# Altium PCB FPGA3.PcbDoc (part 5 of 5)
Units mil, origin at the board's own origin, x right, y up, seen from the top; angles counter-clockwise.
Board outline 4000 x 2750 mil, 12 copper layers (Top Layer, Plane1, MidLayer1, Plane2, MidLayer2, Plane3, Plane4, MidLayer 3, Plane5, MidLayer 4, Plane6, Bottom Layer), stack 57.29 mil thick; 420 components, 368 nets, 1889 pads, 1236 vias.
Unrouted connection lines stored in the file: 1.
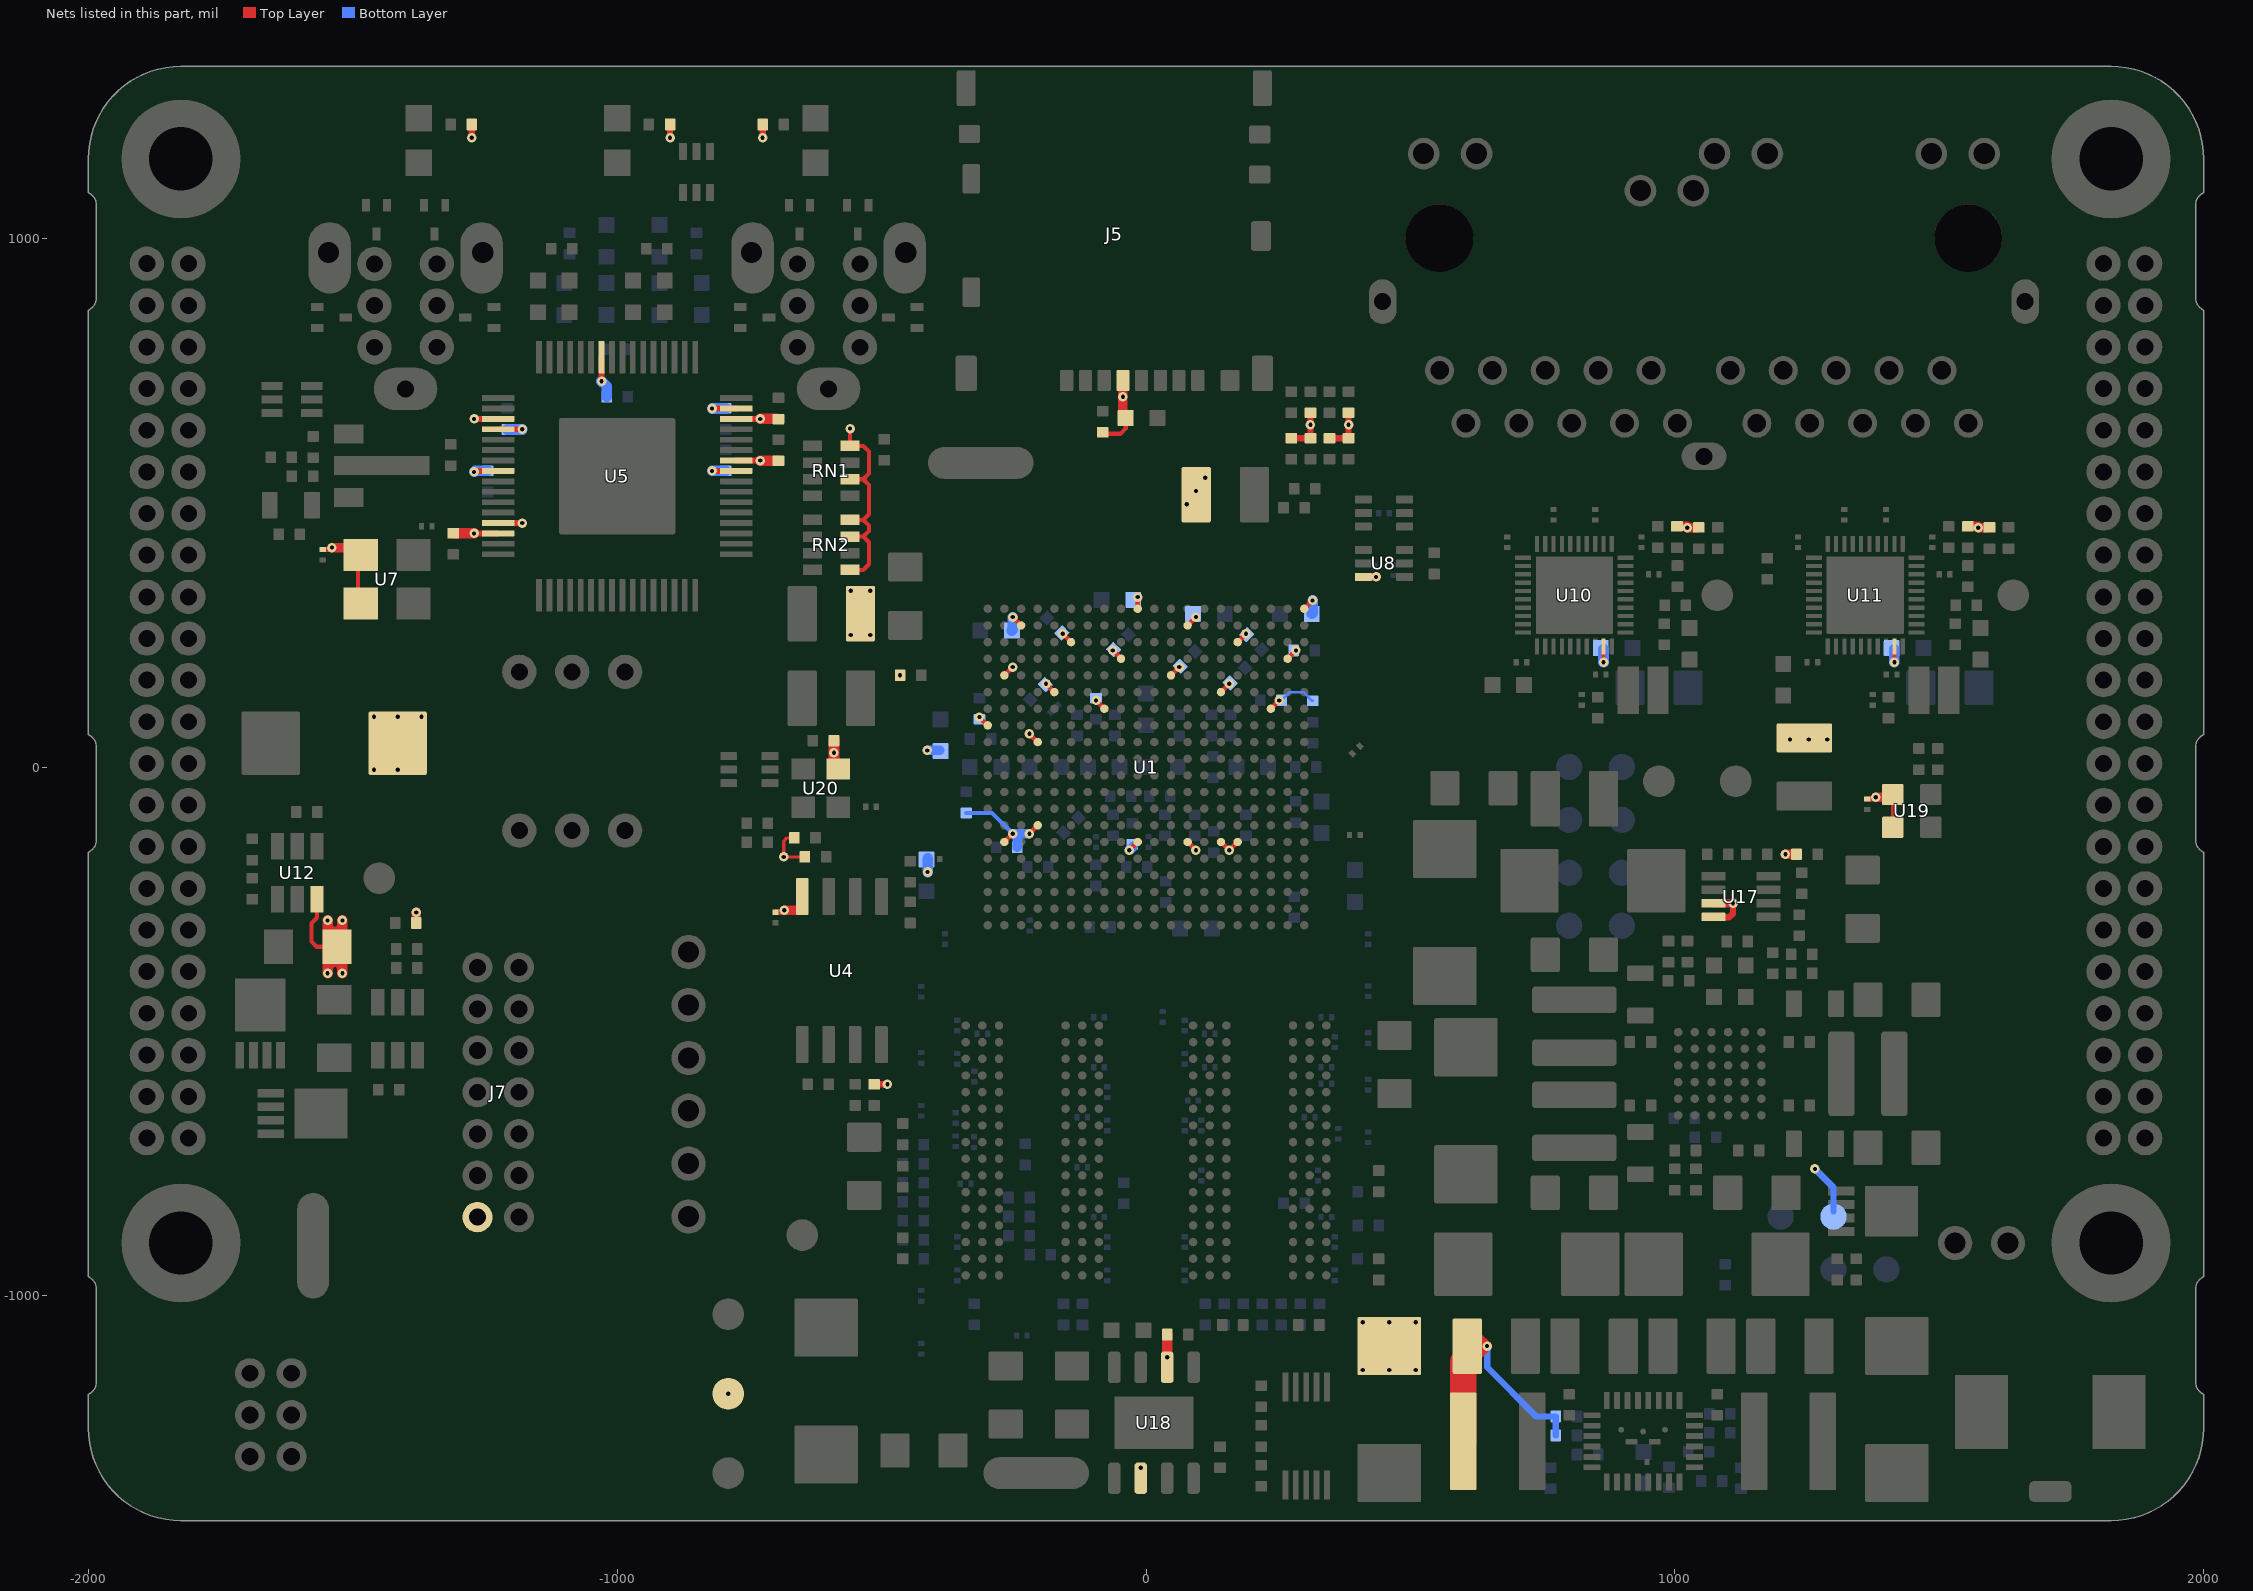
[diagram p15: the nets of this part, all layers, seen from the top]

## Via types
v1: diameter 18, hole 8, Top Layer to Bottom Layer, tented both sides, 1236 vias

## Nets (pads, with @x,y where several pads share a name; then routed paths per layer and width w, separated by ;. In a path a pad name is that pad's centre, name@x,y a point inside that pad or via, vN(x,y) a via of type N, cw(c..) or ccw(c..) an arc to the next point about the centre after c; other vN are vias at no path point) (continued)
VCC3: C5.1 C11.1 C12.1 C13.1 C14.1 C20.1 C26.1 C27.1 C28.1 C29.1 C30.1 C61.1 C62.1 C63.1 C64.1 C72.1 C73.1 CB72.1 CB73.1 CB74.1 CB75.1 CB88.1 CB89.1 CB90.1 CB91.1 CB92.1 CB94.1 CB96.1 CB97.1 CB100.1 CB101.1 CB104.1 CB105.1 CB116.1 CB123.1 CB124.1 CB125.1 CB126.1 CB129.1 CB130.1 CB131.1 CB132.1 J5.4 J7.2 L2.2 L13.2 L14.2 pad.0@-790,-1185 R41.1 R43.1 R46.2 R47.1 R48.2 R49.1 R50.1 R51.1 R52.1 R53.2 R54.2 R55.2 R60.2 R61.1 R64.1 R67.2 R68.1 R70.1 R86.1 R87.1 R104.1 R117.1 RN1.2 RN1.4 RN2.1 RN2.3 RN2.4 TP4.1 U1.A13 U1.B6 U1.B16 U1.C19 U1.D7 U1.D12 U1.E15 U1.F18 U1.H14 U1.J17 U1.K6 U1.K20 U1.M16 U1.N6 U1.N19 U1.R6 U1.R15 U1.T6 U1.T18 U1.V14 U1.W17 U1.Y20 U4.8 U5.25 U5.26 U5.30 U5.31 U5.42 U5.51 U5.52 U5.56 U5.61 U5.62 U7.1 U7.4 U8.6 U10.29 U11.29 U12.6 U17.7 U17.8 U18.2 U18.6 U19.1 U19.4 U20.4 | length 4275.1
  Top Layer w6: R86.1@-672,-141 R86.1@-665,-134 -679,-134 -685,-140 v1(-685,-170) R87.1@-645,-170 ; U20.4@-590,-4 U20.4@-584,-4 ; U19.1@1412,-114 U19.4@1412,-52
  Top Layer w7: U7.4@-1490.37,415 U7.4@-1490,414.63 ; U7.1@-1490,309 U7.4@-1490,399.63
  Top Layer w8: U12.6@-1567.5,-250 -1567.5,-285 -1578,-295.5 -1578,-330 -1568,-340 R117.1@-1533,-340 ; RN2.1@-559.5,372.76 -534.75,372.76 -524,383.5 -524,425 -534.75,435.75 ; RN2.3@-559.5,435.75 -534.75,435.75 ; RN2.4@-559.5,467.24 -534.75,467.24 ; RN1.2@-559.5,544.25 -534.75,544.25 ; v1(-559.5,640) RN1.4@-559.5,607.24 -534.75,607.24 -524,596.5 -524,555 -534.75,544.25 ; R67.2@-82,633 -79,630 -48.5,630 -38.5,640 CB132.1@-38.5,660 ; CB132.1@-43.7,670.7 CB132.1@-43,670 ; v1(865.12,198) U10.29@865.12,228 ; v1(1415.12,198) U11.29@1415.12,228 ; -534.75,435.75 -524,446.5 -524,456.5 -534.75,467.24 ; -534.75,467.24 -524,477.99 -524,533.5 -534.75,544.25
  Top Layer w9: v1(-314.96,94.49) U1.A13@-299.21,78.74 ; U1.B6@-267.72,-141.73 v1(-251.97,-125.98) ; U1.B16@-267.72,173.23 v1(-251.97,188.98) ; v1(-251.97,283.46) U1.C19@-236.22,267.72 ; v1(-220.47,-125.98) U1.D7@-204.72,-110.24 ; v1(-220.47,62.99) U1.D12@-204.72,47.24 ; v1(-188.98,157.48) U1.E15@-173.23,141.73 ; v1(-157.48,251.97) U1.F18@-141.73,236.22 ; v1(-94.49,125.98) U1.H14@-78.74,110.24 ; v1(-62.99,220.47) U1.J17@-47.24,204.72 ; v1(-31.5,-157.48) U1.K6@-15.75,-141.73 ; U1.K20@-15.75,299.21 v1(-15.75,321.48) ; U1.M16@47.24,173.23 v1(62.99,188.98) ; U1.N6@78.74,-141.73 v1(94.49,-157.48) ; U1.N19@78.74,267.72 v1(94.49,283.46) ; U1.R6@141.73,-141.73 v1(157.48,-157.48) U1.T6@173.23,-141.73 ; U1.R15@141.73,141.73 v1(157.48,157.48) ; U1.T18@173.23,236.22 v1(188.98,251.97) ; U1.V14@236.22,110.24 v1(251.97,125.98) ; U1.W17@267.72,204.72 v1(283.46,220.47) ; U1.Y20@299.21,299.21 v1(314.96,314.96)
  Top Layer w10: CB74.1@-1554.29,411.5 v1@-1539.29,411.5 ; v1@-1540.45,415 v1(-1539.37,415) v1@-1538.29,415 ; CB75.1@-698.92,-274.5 v1@-683.92,-274.5 ; v1@-685.08,-271 v1(-684,-271) v1@-682.92,-271 ; CB73.1@1364,-60.5 v1@1379,-60.5 ; v1@1377.84,-57 v1(1380,-57)
  Top Layer w11: v1(-1270.47,441.73) U5.62@-1225,441.73 ; v1@-1270.47,559.84 U5.56@-1225,559.84 ; v1(-1270.47,658.27) U5.51@-1225,658.27 ; U5.61@-1225,461.42 v1(-1179.53,461.42) ; U5.52@-1225,638.58 v1(-1179.53,638.58) ; v1(-1029.53,729.53) U5.42@-1029.53,775 ; v1(-820.47,559.84) U5.25@-775,559.84 ; v1(-820.47,677.95) U5.31@-775,677.95 ; U5.26@-775,579.53 v1(-729.53,579.53) ; U5.30@-775,658.27 v1(-729.53,658.27)
  Top Layer w12: v1(-1275,1190) R46.2@-1275,1215 ; v1(-900,1190) R47.1@-900,1215 ; v1(-725,1190) R48.2@-725,1215 ; R54.2@-514,-600 v1(-489,-600) ; R49.1@275,622 R50.1@311,622 v1(311,647) R41.1@311,670 ; R51.1@347,622 R52.1@383,622 v1(383,647) R43.1@383,670 ; U17.8@1073,-283.39 1073.57,-283.95 1102.97,-283.95 1110,-276.92 v1(1110,-257.8)
  Top Layer w15: U8.6@411,359.41 v1(435,359.41)
  Top Layer w16: U17.7@1073,-257.8 v1(1110,-257.8)
  Top Layer w18: v1@-1538.29,415 U7.4@-1490.37,415 ; R61.1@-1380,-295 v1(-1380,-275) ; v1(-684,-271) U4.8@-658,-271 ; CB132.1@-43.7,670.7 v1(-43.7,700) J5.4@-43.7,730.83 ; C64.1@627.32,-1112.68 v1(645,-1095) C64.1@627.32,-1077.32 ; L13.2@1004,455 v1@1023.5,455 ; v1(1023.5,452.5) R68.1@1043,452.5 ; v1(1209,-165) R64.1@1230,-165 ; v1(1380,-57) U19.4@1401,-57 ; L14.2@1554,455 v1@1573.5,455 ; v1(1573.5,452.5) R70.1@1593,452.5
  Top Layer w20: v1(-1547.5,-390) v1@-1547.5,-382 ; R117.1@-1547.5,-345 v1@-1547.5,-382 ; R117.1@-1547.5,-335 v1@-1547.5,-298.05 ; v1(-1547.5,-290) v1@-1547.5,-298 ; v1(-1519.5,-390) v1@-1519.5,-382 ; R117.1@-1519.5,-345 v1@-1519.5,-382 ; R117.1@-1519.5,-335 v1@-1519.5,-298.05 ; v1(-1519.5,-290) v1@-1519.5,-298 ; C11.1@-1310,442 -1309.73,441.73 v1(-1270.47,441.73) ; v1(-729.53,579.53) -695.31,579.53 C13.1@-695,579.21 ; v1(-729.53,658.27) C12.1@-698.06,658.27 ; U20.4@-590,-8 -590,-4 -590,2 v1(-590,27) C14.1@-590,50 ; U18.6@40,-1135 v1(40,-1116) 40,-1074 C20.1@40,-1073 ; v1@-1547.5,-382 cw(c-1533.5,-382) v1@-1519.5,-382 ; v1@-1547.5,-382 cw(c-1533.5,-382) v1@-1519.5,-382 ; v1@-1547.5,-298.05 ccw(c-1533.5,-298) v1@-1519.5,-298.05 ; v1@-1547.5,-298.05 ccw(c-1533.5,-298) v1@-1519.5,-298.05 ; v1@-1547.5,-298.05 cw(c-1533.5,-298) v1@-1547.5,-298 ; v1@-1547.5,-298.05 cw(c-1533.5,-298) v1@-1547.5,-298 ; v1@-1547.5,-298.05 v1@-1547.5,-298 ; v1@-1519.5,-298.05 ccw(c-1533.5,-298) v1@-1519.5,-298 ; v1@-1519.5,-298.05 ccw(c-1533.5,-298) v1@-1519.5,-298 ; v1@-1519.5,-298.05 v1@-1519.5,-298
  Top Layer w25: U20.4@-590,2 U20.4@-584,-4
  Top Layer w50: L2.2@600,-1275 C64.1@600,-1125
  Bottom Layer w5: CB97.1@256.22,125.98 271.97,141.73 298.27,141.73 306.5,133.5 306.5,132.5 314,125 R60.2@315,125
  Bottom Layer w8: R55.2@-340,-87 -290.95,-87 v1(-251.97,-125.98)
  Bottom Layer w12: v1(645,-1095) 645,-1135 738,-1228 C5.1@775,-1228 R104.1@775,-1264 ; v1(1265,-760) 1300,-795 TP4.1@1300,-840
  Bottom Layer w18: v1(-413.5,31.5) CB116.1@-390,31.5 ; v1(-251.97,-125.98) v1@-243.5,-125.98 ; CB90.1@-243.5,-152 v1@-243.5,-125.98 ; v1(-220.47,-125.98) v1@-243.5,-125.98 ; v1(-31.5,-157.48) CB94.1@-23.98,-149.97
  Bottom Layer w20: v1(-1270.47,558) -1268.47,560 C30.1@-1245,560 ; C29.1@-1208,638.27 -1179.84,638.27 v1(-1179.53,638.58) ; v1(-1029.53,729.53) -1020,720 C28.1@-1020,700 ; v1(-820.47,559.84) -820.31,560 C27.1@-795,560 ; v1(-820.47,677.95) -795.31,677.95 C26.1@-795,678.27 ; v1(-413,-198.5) CB129.1@-413,-173 ; CB125.1@-253.46,258 -251.97,259.5 v1(-251.97,283.46) ; CB123.1@313.46,289.5 314.96,291 v1(314.96,314.96) ; v1(865.12,198) CB130.1@865.12,223 ; v1(1415.12,198) CB131.1@1415.12,223
  other v1: -10,-1325 -790,-1185 410,-1140 460,-1140 510,-1140 410,-1050 460,-1050 510,-1050 -1460,-5 -1415,-5 1218,52 1253,52 1288,52 -1460,95 -1415,95 -1370,95 -465,173.5 -558.5,249.5 -521.5,249.5 -558.5,333.5 -521.5,333.5 77,497 94.5,522 112,547
pads on no net: J3.1 J4.1 J5.9 J5.10 J7.12 J7.14 J8.5 J8.6 J8.10A J8.10B J10.3 U1.A14 U1.A15 U1.A16 U1.A17 U1.A19 U1.B5 U1.B14 U1.B17 U1.B18 U1.C5 U1.C6 U1.C8 U1.C10 U1.C11 U1.C13 U1.C15 U1.C16 U1.C18 U1.D9 U1.D10 U1.D11 U1.D13 U1.D15 U1.E6 U1.E8 U1.E9 U1.E11 U1.E13 U1.E14 U1.E16 U1.F10 U1.F14 U1.F15 U1.N16 U2.J1 U2.J9 U2.L1 U2.L9 U2.M7 U3.J1 U3.J9 U3.L1 U3.L9 U3.M7 U5.3 U5.16 U5.60 U6.2 U6.4 U6.5 U10.32 U10.35 U11.32 U11.35 U14.6 U14.7 U15.E2 U15.E5 U16.6 U16.10 U16.27

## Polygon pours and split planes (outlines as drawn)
GND on MidLayer 4 "Mid4GND" (hatched 90Degree grid 8 track 8.1, remove dead copper, pour order 3): -2000,-1425 2000,-1425 2000,1325 -2000,1325
GND on MidLayer 3 "Mid3GND" (hatched 90Degree grid 8 track 8.1, remove dead copper, pour order 2): -2025,-1438 1975,-1438 1975,1312 -2025,1312
GND on MidLayer2 "Mid2GND" (hatched 90Degree grid 8 track 8.1, remove dead copper, pour order 1): -2000,-1425 2000,-1425 2000,1325 -2000,1325
GND on MidLayer1 "Mid1GND" (hatched 90Degree grid 8 track 8.1, remove dead copper, pour order 0): -2000,-1425 2000,-1425 2000,1325 -2000,1325
GND on Plane1 (split plane): 225 vertices, not listed, extent -1979.97,-1404.97 1979.97,1304.97
GND on Plane2 (split plane): 225 vertices, not listed, extent -1979.97,-1404.97 1979.97,1304.97
5V on Plane2 (split plane): -740.1,-5 -739.71,-6.95 -738.6,-8.6 -605.1,-142.11 -605.1,-890 -604.71,-891.95 -603.6,-893.6 -505.1,-992.11 -505.1,-1329.9 -1602.89,-1329.9 -1644.9,-1287.89 -1644.9,-282.11 -1581.4,-218.6 -1580.29,-216.95 -1579.9,-215 -1579.9,105 -1580.29,106.95 -1581.4,108.6 -1604.9,132.11 -1604.9,399.9 -740.1,399.9
V-FAULT_3 on Plane2 (split plane): -410.1,675 -409.71,673.05 -408.6,671.4 -358.6,621.4 -356.95,620.29 -355,619.9 829.9,619.9 829.9,570.1 -575,570.1 -576.95,569.71 -578.6,568.6 -737.11,410.1 -1604.9,410.1 -1604.9,1069.9 -410.1,1069.9
5V-DCDC_10 on Plane2 (split plane): 1519.9,-1287.89 1477.89,-1329.9 -494.9,-1329.9 -494.9,-1225.1 125,-1225.1 126.95,-1224.71 128.6,-1223.6 157.11,-1195.1 385,-1195.1 386.95,-1194.71 388.6,-1193.6 528.6,-1053.6 529.71,-1051.95 530.1,-1050 530.1,-430.1 935,-430.1 936.95,-429.71 938.6,-428.6 988.6,-378.6 1102.11,-265.1 1519.9,-265.1
0.75V on Plane2 (split plane): 261.4,-163.6 263.05,-164.71 265,-165.1 297.89,-165.1 506.4,-373.6 519.9,-387.11 519.9,-1047.89 382.89,-1184.9 155,-1184.9 153.05,-1185.29 151.4,-1186.4 122.89,-1214.9 -494.9,-1214.9 -494.9,-990 -495.29,-988.05 -496.4,-986.4 -594.9,-887.89 -594.9,-145.1 242.89,-145.1
1.8V on Plane2 (split plane): 1519.9,317.89 1519.9,-254.9 1100,-254.9 1098.05,-255.29 1096.4,-256.4 981.4,-371.4 932.89,-419.9 530.1,-419.9 530.1,-385 529.71,-383.05 528.6,-381.4 513.6,-366.4 303.6,-156.4 301.95,-155.29 300,-154.9 267.11,-154.9 248.6,-136.4 246.95,-135.29 245,-134.9 -597.89,-134.9 -729.9,-2.89 -729.9,402.89 -572.89,559.9 1033.51,559.9 1034.11,559.76 1038.5,559.41 1038.5,559.44 1071.5,559.44 1071.5,559.41 1075.89,559.76 1076.49,559.9 1277.89,559.9
GND on Plane3 (split plane): 225 vertices, not listed, extent -1979.97,-1404.97 1979.97,1304.97
1.5V on Plane3 (split plane): 926.4,-748.6 928.05,-749.71 930,-750.1 1019.9,-750.1 1019.9,-827.89 1002.89,-844.9 930,-844.9 928.05,-845.29 926.4,-846.4 437.89,-1334.9 -511.17,-1334.9 -800.54,-1045.54 -800.74,-1045.4 -802.45,-1043.32 -803.83,-1040.73 -804.68,-1037.92 -804.97,-1035 -804.68,-1032.08 -803.83,-1029.27 -802.45,-1026.68 -800.74,-1024.6 -800.54,-1024.46 -596.4,-820.32 -595.29,-818.67 -594.9,-816.72 -594.9,-162.6 340.39,-162.6
1.0V on Plane3 (split plane): 709.9,190 710.29,188.05 711.4,186.4 801.4,96.4 803.05,95.29 805,94.9 1594.9,94.9 1594.9,-622.89 1477.89,-739.9 932.11,-739.9 346.1,-153.9 344.45,-152.79 342.5,-152.4 -594.9,-152.4 -594.9,317.89 -572.89,339.9 -425,339.9 -423.05,340.29 -421.4,341.4 -407.89,354.9 709.9,354.9
NetC58_1 on Plane3 (split plane): 1144.9,105.1 807.11,105.1 720.1,192.11 720.1,269.9 1144.9,269.9
NetC57_1 on Plane3 (split plane): 1594.9,105.1 1155.1,105.1 1155.1,269.9 1594.9,269.9
NetC36_1 on Plane3 (split plane): 1144.9,280.1 720.1,280.1 720.1,467.89 767.11,514.9 1144.9,514.9
NetC39_1 on Plane3 (split plane): 1594.9,432.89 1594.9,280.1 1155.1,280.1 1155.1,514.9 1512.89,514.9
GND on Plane4 (split plane): 225 vertices, not listed, extent -1979.97,-1404.97 1979.97,1304.97
GND on Plane5 (split plane): 225 vertices, not listed, extent -1979.97,-1404.97 1979.97,1304.97
VCC3 on Plane5 (split plane): -578.6,1066.4 -576.95,1065.29 -575,1064.9 1597.89,1064.9 1694.9,967.89 1694.9,-907.89 1272.89,-1329.9 10,-1329.9 8.05,-1330.29 6.4,-1331.4 2.89,-1334.9 -22.89,-1334.9 -26.4,-1331.4 -28.05,-1330.29 -30,-1329.9 -937.89,-1329.9 -1624.9,-642.89 -1624.9,-97.11 -1581.4,-53.6 -1580.29,-51.95 -1579.9,-50 -1579.9,1022.89 -1397.89,1204.9 -717.11,1204.9
GND on Plane5 (split plane): 131.18,-150.29 132.97,-151.03 134.52,-152.22 135.7,-153.76 136.44,-155.55 136.67,-157.3 136.63,-157.48 136.69,-157.77 136.92,-160.74 137.69,-163.91 138.94,-166.93 140.64,-169.71 142.76,-172.2 145.25,-174.32 148.03,-176.02 151.05,-177.27 154.23,-178.04 157.48,-178.29 160.74,-178.04 163.91,-177.27 166.93,-176.02 169.71,-174.32 172.2,-172.2 174.32,-169.71 176.02,-166.93 177.27,-163.91 178.04,-160.74 178.27,-157.77 178.33,-157.48 178.29,-157.3 178.52,-155.55 179.26,-153.76 180.45,-152.22 181.99,-151.03 183.78,-150.29 185.52,-150.06 185.71,-150.1 342.89,-150.1 464.9,-272.11 464.9,-947.89 312.89,-1099.9 72.11,-1099.9 63.6,-1091.4 61.95,-1090.29 60,-1089.9 5,-1089.9 3.05,-1090.29 1.4,-1091.4 -7.11,-1099.9 -439.9,-1099.9 -439.9,-272.11 -317.89,-150.1 -59.73,-150.1 -59.54,-150.06 -57.8,-150.29 -56,-151.03 -54.46,-152.22 -53.28,-153.76 -52.53,-155.55 -52.31,-157.3 -52.34,-157.48 -52.29,-157.77 -52.05,-160.74 -51.29,-163.91 -50.04,-166.93 -48.33,-169.71 -46.21,-172.2 -43.73,-174.32 -40.94,-176.02 -37.93,-177.27 -34.75,-178.04 -31.5,-178.29 -28.24,-178.04 -25.07,-177.27 -22.05,-176.02 -19.26,-174.32 -16.78,-172.2 -14.66,-169.71 -12.95,-166.93 -11.7,-163.91 -10.94,-160.74 -10.71,-157.77 -10.65,-157.48 -10.69,-157.3 -10.46,-155.55 -9.71,-153.76 -8.53,-152.22 -6.99,-151.03 -5.19,-150.29 -3.45,-150.06 -3.27,-150.1 66.26,-150.1 66.45,-150.06 68.19,-150.29 69.98,-151.03 71.52,-152.22 72.71,-153.76 73.45,-155.55 73.68,-157.3 73.64,-157.48 73.7,-157.77 73.93,-160.74 74.69,-163.91 75.94,-166.93 77.65,-169.71 79.77,-172.2 82.26,-174.32 85.04,-176.02 88.06,-177.27 91.23,-178.04 94.49,-178.29 97.74,-178.04 100.92,-177.27 103.94,-176.02 106.72,-174.32 109.2,-172.2 111.33,-169.71 113.03,-166.93 114.28,-163.91 115.04,-160.74 115.28,-157.77 115.34,-157.48 115.33,-157.48 115.3,-157.3 115.53,-155.55 116.27,-153.76 117.45,-152.22 119,-151.03 120.79,-150.29 122.53,-150.06 122.72,-150.1 129.25,-150.1 129.44,-150.06
GND on Plane6 (split plane): 225 vertices, not listed, extent -1979.97,-1404.97 1979.97,1304.97

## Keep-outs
MidLayer1:
  lines w15: -1995,-1188.98 ccw(c-2010,-1163) -1980,-1163 -1980,-987 ccw(c-2010,-987) -1995,-961.02 ; -1995,-163.98 ccw(c-2010,-138) -1980,-138 -1980,38 ccw(c-2010,38) -1995,63.98 ; -1995,861.02 ccw(c-2010,887) -1980,887 -1980,1063 ccw(c-2010,1063) -1995,1088.98 ; 1995,-1188.98 cw(c2010,-1163) 1980,-1163 1980,-987 cw(c2010,-987) 1995,-961.02 ; 1995,-163.98 cw(c2010,-138) 1980,-138 1980,38 cw(c2010,38) 1995,63.98 ; 1995,861.02 cw(c2010,887) 1980,887 1980,1063 cw(c2010,1063) 1995,1088.98 ; -1995,-1250 ccw(c-1825,-1250) -1825,-1420 1825,-1420 ccw(c1825,-1250) 1995,-1250 1995,1150 ccw(c1825,1150) 1825,1320 -1825,1320 ccw(c-1825,1150) -1995,1150 -1995,-1250
MidLayer2:
  lines w15: -1995,-1188.98 ccw(c-2010,-1163) -1980,-1163 -1980,-987 ccw(c-2010,-987) -1995,-961.02 ; -1995,-163.98 ccw(c-2010,-138) -1980,-138 -1980,38 ccw(c-2010,38) -1995,63.98 ; -1995,861.02 ccw(c-2010,887) -1980,887 -1980,1063 ccw(c-2010,1063) -1995,1088.98 ; 1995,-1188.98 cw(c2010,-1163) 1980,-1163 1980,-987 cw(c2010,-987) 1995,-961.02 ; 1995,-163.98 cw(c2010,-138) 1980,-138 1980,38 cw(c2010,38) 1995,63.98 ; 1995,861.02 cw(c2010,887) 1980,887 1980,1063 cw(c2010,1063) 1995,1088.98 ; -1995,-1250 ccw(c-1825,-1250) -1825,-1420 1825,-1420 ccw(c1825,-1250) 1995,-1250 1995,1150 ccw(c1825,1150) 1825,1320 -1825,1320 ccw(c-1825,1150) -1995,1150 -1995,-1250
MidLayer 3:
  lines w15: -1995,-1188.98 ccw(c-2010,-1163) -1980,-1163 -1980,-987 ccw(c-2010,-987) -1995,-961.02 ; -1995,-163.98 ccw(c-2010,-138) -1980,-138 -1980,38 ccw(c-2010,38) -1995,63.98 ; -1995,861.02 ccw(c-2010,887) -1980,887 -1980,1063 ccw(c-2010,1063) -1995,1088.98 ; 1995,-1188.98 cw(c2010,-1163) 1980,-1163 1980,-987 cw(c2010,-987) 1995,-961.02 ; 1995,-163.98 cw(c2010,-138) 1980,-138 1980,38 cw(c2010,38) 1995,63.98 ; 1995,861.02 cw(c2010,887) 1980,887 1980,1063 cw(c2010,1063) 1995,1088.98 ; -1995,-1250 ccw(c-1825,-1250) -1825,-1420 1825,-1420 ccw(c1825,-1250) 1995,-1250 1995,1150 ccw(c1825,1150) 1825,1320 -1825,1320 ccw(c-1825,1150) -1995,1150 -1995,-1250
MidLayer 4:
  lines w15: -1995,-1188.98 ccw(c-2010,-1163) -1980,-1163 -1980,-987 ccw(c-2010,-987) -1995,-961.02 ; -1995,-163.98 ccw(c-2010,-138) -1980,-138 -1980,38 ccw(c-2010,38) -1995,63.98 ; -1995,861.02 ccw(c-2010,887) -1980,887 -1980,1063 ccw(c-2010,1063) -1995,1088.98 ; 1995,-1188.98 cw(c2010,-1163) 1980,-1163 1980,-987 cw(c2010,-987) 1995,-961.02 ; 1995,-163.98 cw(c2010,-138) 1980,-138 1980,38 cw(c2010,38) 1995,63.98 ; 1995,861.02 cw(c2010,887) 1980,887 1980,1063 cw(c2010,1063) 1995,1088.98 ; -1995,-1250 ccw(c-1825,-1250) -1825,-1420 1825,-1420 ccw(c1825,-1250) 1995,-1250 1995,1150 ccw(c1825,1150) 1825,1320 -1825,1320 ccw(c-1825,1150) -1995,1150 -1995,-1250
Bottom Layer:
  lines w5: -35,-1420 -1825,-1420 cw(c-1825,-1250) -1995,-1250 -1995,1150 cw(c-1825,1150) -1825,1320 1825,1320 cw(c1825,1150) 1995,1150 1995,-1250 cw(c1825,-1250) 1825,-1420 35,-1420

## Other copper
Top Layer:
  rectangle net GND: 921,-1299 970,-1275
  rectangle net GND: 872.53,-1322.47 930.16,-1275
  rectangle net GND: 962,-1322.47 1007.47,-1276
  rectangle net GND: 930,-1275 949.84,-1225
  rectangle net V-IN_10: 913,-1149 967,-1140
  rectangle net NetD2_1: -802.5,-50 -784.5,-32.59
  rectangle net GND: -1455,515 -1355,625
  rectangle net V-FAULT_3: -1575,470 -1480,520
  rectangle net GND: -240,-1270 -160,-1225
  rectangle net 0.75V: -245,-1150 -160,-1105
  region net VCC3: 592.5,-1042.5 510,-1042.5 510,-1150 592.5,-1150
  rectangle net 1.0V: 1430,-660 1464.5,-500
  rectangle net 1.0V: 1447.5,-720 1502.5,-440
  rectangle net NetL15_1: 1227.5,-829.5 1275,-805
  rectangle net V-IN_10: 967,-1170.16 1010,-1140
  rectangle net 0.75V: -125,-1165 -60,-1105
  rectangle net V-IN_10: 871.1,-1050 1008.9,-880
  rectangle net GND: 1105,-1147.5 1141,-1042.5
  rectangle net NetC58_1: 720,189 734.13,198
  region net 1.8V: 780,-425 780,-335 730,-335 730,-425
  region net 1.5V: 730,-735 730,-825 780,-825 780,-735
  rectangle net GND: 1312.5,-472.5 1350,-422.5
  rectangle net GND: 1312.5,-737.5 1350,-687.5
  region net NetC21_1: 135,-1335 135,-1315 95,-1315 95,-1335
  rectangle net 5V-DCDC_10: 239,-1369 262,-1351
  rectangle net 5V-DCDC_10: 1287.5,-1150 1370,-1042.5
  region net GND: 775,-1042.5 739,-1042.5 739,-1147.5 775,-1147.5
  rectangle net V-IN_10: 871.1,-1170.16 913,-1140
  region net 5V-DCDC_10: 1225,-515 1225,-422.5 1195,-422.5 1195,-515
  region net 5V-DCDC_10: 975,-515 975,-455 945,-455 945,-515
  region net 5V-DCDC_10: 1195,-645 1195,-737.5 1225,-737.5 1225,-645
  region net NetL3_1: 1215,-570 1215,-590 1310,-590 1310,-570
  region net GND: 951.02,-387.5 951.02,-337.5 852,-337.5 852,-387.5
  region net 5V-DCDC_10: 945,-645 945,-705 975,-705 975,-645
  region net NetL4_1: 820,-615 820,-584 730,-584 730,-615
  region net GND: 851.5,-772.5 851.5,-822.5 950.52,-822.5 950.52,-772.5
  region net NetL5_1: 730,-545 730,-576 820,-576 820,-545
  rectangle net V-IN_10: 913,-1147.5 967,-1042.5
  rectangle net NetC23_1: 800,-1196 832.5,-1176
  region net NetC24_1: 1080,-1176 1047.5,-1176 1047.5,-1196 1080,-1196
  region net NetC24_2: 1004.32,-1227.53 969.84,-1227.53 969.84,-1255.69 1004.32,-1255.69
  rectangle net NetC23_2: 876,-1255.69 910.47,-1227.53
  rectangle net 5V: -1450,-470 -1436,-420
  rectangle net NetQ2_5: -1722.5,-420 -1627.5,-307.5
  rectangle net 3.3V-OUT_2: -1810.63,-570 -1662.2,-520
  region net NetQ1_5: -1547.5,-607.5 -1547.5,-702.5 -1502.5,-702.5 -1502.5,-607.5
  rectangle net NetQ1_5: -1430,-470 -1415,-420
  rectangle net 5V-OUT_2: -1730,-670 -1655,-590.53
  rectangle net NetQ2_4: -1640,-570 -1610,-550
  rectangle net NetQ1_5: -1567.5,-620 -1502.5,-562.5
MidLayer1:
  rectangle net GND: 136,321.48 150.73,335
  pour cut-out: 1065,-675 ccw(c1085,-675) 1105,-675 1105,-485 ccw(c1085,-485) 1065,-485
  pour cut-out: -400,-975 -300,-1075 300,-1075 420,-955 420,180 265,335 -265,335 -400,200
  pour cut-out: -1570,1016 -1570,775 -1525,730 -470,730 -425,775 -425,1016 -670,1016 -745,1016
MidLayer2:
  pour cut-out: 1065,-675 ccw(c1085,-675) 1105,-675 1105,-485 ccw(c1085,-485) 1065,-485
  pour cut-out: -400,-975 -300,-1075 -100,-1075 -85,-1090 285,-1090 400,-975 400,200 265,335 -265,335 -400,200
MidLayer 3:
  pour cut-out: 1065,-675 ccw(c1085,-675) 1105,-675 1105,-485 ccw(c1085,-485) 1065,-485
  pour cut-out: -400,-625 -425,-650 -425,-950 -300,-1075 300,-1075 400,-975 400,325 390,335 -390,335 -400,325
MidLayer 4:
  pour cut-out: 1065,-675 ccw(c1085,-675) 1105,-675 1105,-485 ccw(c1085,-485) 1065,-485
  pour cut-out: -400,-975 -300,-1075 300,-1075 400,-975 400,325 390,335 -390,335 -400,325
Bottom Layer:
  rectangle net GND: 1114,-1380 1136,-1365
  rectangle net INTVCC_10: 949,-1378 958.84,-1340
  region net GND: 876,-1289 861,-1289 861,-1311 876,-1311
  rectangle net GND: 1004,-1306 1019,-1284
  region net NetC7_1: -1030,980 -1039.62,980 -1039.62,957 -1030,957
  rectangle net GND: 905,180.5 947.5,212.5
  rectangle net GND: 1455,180.5 1497.5,212.5
  rectangle net NetC57_1: 1529,126.5 1571.5,176
  rectangle net NetC58_1: 979,126.5 1021.5,176
  rectangle net CLK_7_N: -239,-755 -217,-740
  rectangle net CLK_7_P: -239,-725 -217,-714
  rectangle net NetC6_1: -935,920 -825,952.5
  rectangle net NetC6_1: -910,900 -896,923
  region net NetC6_1: -850,923 -864,923 -864,900 -850,900
  rectangle net NetC6_1: -910,950 -900.38,980
  region net NetC6_1: -839,964 -922,964 -922,950 -839,950
  rectangle net NetC7_1: -1101,944.5 -1005,964
  region net NetC7_1: -1030,923 -1044,923 -1044,900 -1030,900
  rectangle net NetC7_1: -1090,900 -1076,923
  rectangle net GND: -910,1010 -839,1040
  rectangle net GND: -1101,1010 -1030,1040
  rectangle net NetC7_1: -1115,920 -1005,952.5
Plane3 (plane layer: these items are gaps in the copper):
  circle w30: c-540.95,793.74 r13
  circle w30: c1555,650 r14.5
  circle w30: c1005,650 r14.5
  circle w30: c-1085,-120 r13
  circle w30: c-1085,180 r13
  circle w34: c-865,-850 r15
  circle w30: c-1185.63,-851.22 r13
  circle w30: c-1185.63,-772.48 r13
  circle w30: c-1185.63,-693.74 r13
  circle w30: c-1185.63,-615 r13
  circle w30: c-1185.63,-536.26 r13
  circle w30: c-1185.63,-457.52 r13
  circle w30: c-1185.63,-378.78 r13
  circle w30: c-1615.63,-1146.26 r13
  circle w30: c-1615.63,-1146.26 r13
  circle w30: c-1185.63,-378.78 r13
  circle w30: c-1185.63,-457.52 r13
  circle w30: c-1185.63,-536.26 r13
  circle w30: c-1185.63,-615 r13
  circle w30: c-1185.63,-693.74 r13
  circle w30: c-1185.63,-772.48 r13
  circle w30: c-1185.63,-851.22 r13
  circle w34: c-865,-850 r15
  circle w30: c-1340.95,793.74 r13
  circle w31: c1630,-900 r15
  circle w27: c1889.37,951.77 r13
  circle w27: c1889.37,400.59 r13
  circle w27: c1889.37,-150.59 r13
  circle w27: c1889.37,-701.77 r13
  circle w27: c-1889.37,-701.77 r13
  circle w27: c-1889.37,-465.55 r13
  circle w27: c-1810.63,-465.55 r13
  circle w27: c-1889.37,6.89 r13
  circle w27: c-1889.37,479.33 r13
  circle w27: c-1889.37,951.77 r13
  lines w10: -600,-157.5 342.5,-157.5 930,-745 1480,-745 1600,-625 1600,435 ; 715,275 1600,275 ; 715,360 -410,360 -425,345 -575,345 -600,320 -600,-816.72 -804.14,-1020.86 ccw(c-790,-1035) -804.14,-1049.14 -513.28,-1340 440,-1340 930,-850 1005,-850 1025,-830 1025,-745 ; 1150,100 1150,520 ; 1600,435 1515,520 765,520 715,470 715,190 805,100 1600,100 1600,435
  lines w15: -1569.73,950.87 ccw(c-1545.73,950.87) -1521.73,950.87 -1521.73,994.87 ccw(c-1545.73,994.87) -1569.73,994.87 -1569.73,950.87 ; -1425,695 cw(c-1425,715) -1425,735 -1375,735 cw(c-1375,715) -1375,695 -1425,695 ; -1278.27,950.87 ccw(c-1254.27,950.87) -1230.27,950.87 -1230.27,994.87 ccw(c-1254.27,994.87) -1278.27,994.87 -1278.27,950.87 ; -769.73,950.87 ccw(c-745.73,950.87) -721.73,950.87 -721.73,994.87 ccw(c-745.73,994.87) -769.73,994.87 -769.73,950.87 ; -625,695 cw(c-625,715) -625,735 -575,735 cw(c-575,715) -575,695 -625,695 ; -478.27,950.87 ccw(c-454.27,950.87) -430.27,950.87 -430.27,994.87 ccw(c-454.27,994.87) -478.27,994.87 -478.27,950.87 ; 427,863.5 ccw(c447.5,863.5) 468,863.5 468,896.5 ccw(c447.5,896.5) 427,896.5 427,863.5 ; 1038.5,567 cw(c1038.5,587.5) 1038.5,608 1071.5,608 cw(c1071.5,587.5) 1071.5,567 1038.5,567 ; 1642,863.5 ccw(c1662.5,863.5) 1683,863.5 1683,896.5 ccw(c1662.5,896.5) 1642,896.5 1642,863.5
  lines w32: -1424,715 -1376,715 ; -624,715 -576,715 ; 447.5,863.5 447.5,896.5 ; 1038.5,587.5 1071.5,587.5 ; 1662.5,863.5 1662.5,896.5
  lines w40: -1545.73,950.87 -1545.73,994.87 ; -1254.27,950.87 -1254.27,994.87 ; -745.73,950.87 -745.73,994.87 ; -454.27,950.87 -454.27,994.87
Plane4 (plane layer: these items are gaps in the copper):
  circle w30: c-540.95,793.74 r13
  circle w30: c-1340.95,793.74 r13
  circle w30: c1555,650 r14.5
  circle w30: c1005,650 r14.5
  circle w30: c-1615.63,-1146.26 r13
  circle w30: c-1185.63,-772.48 r13
  circle w30: c-1185.63,-693.74 r13
  circle w30: c-1185.63,-615 r13
  circle w30: c-1185.63,-536.26 r13
  circle w30: c-1185.63,-457.52 r13
  circle w30: c-1185.63,-378.78 r13
  circle w30: c-1185.63,-851.22 r13
  circle w34: c-865,-850 r15
  circle w30: c-1085,180 r13
  circle w30: c-1085,-120 r13
  circle w27: c1889.37,951.77 r13
  circle w27: c1889.37,400.59 r13
  circle w27: c1889.37,-150.59 r13
  circle w27: c1889.37,-701.77 r13
  circle w27: c-1889.37,-701.77 r13
  circle w27: c-1889.37,-465.55 r13
  circle w27: c-1810.63,-465.55 r13
  circle w27: c-1889.37,6.89 r13
  circle w27: c-1889.37,479.33 r13
  circle w27: c-1889.37,951.77 r13
  lines w15: -1569.73,950.87 ccw(c-1545.73,950.87) -1521.73,950.87 -1521.73,994.87 ccw(c-1545.73,994.87) -1569.73,994.87 -1569.73,950.87 ; -1425,695 cw(c-1425,715) -1425,735 -1375,735 cw(c-1375,715) -1375,695 -1425,695 ; -1278.27,950.87 ccw(c-1254.27,950.87) -1230.27,950.87 -1230.27,994.87 ccw(c-1254.27,994.87) -1278.27,994.87 -1278.27,950.87 ; -769.73,950.87 ccw(c-745.73,950.87) -721.73,950.87 -721.73,994.87 ccw(c-745.73,994.87) -769.73,994.87 -769.73,950.87 ; -625,695 cw(c-625,715) -625,735 -575,735 cw(c-575,715) -575,695 -625,695 ; -478.27,950.87 ccw(c-454.27,950.87) -430.27,950.87 -430.27,994.87 ccw(c-454.27,994.87) -478.27,994.87 -478.27,950.87 ; 427,863.5 ccw(c447.5,863.5) 468,863.5 468,896.5 ccw(c447.5,896.5) 427,896.5 427,863.5 ; 1038.5,567 cw(c1038.5,587.5) 1038.5,608 1071.5,608 cw(c1071.5,587.5) 1071.5,567 1038.5,567 ; 1642,863.5 ccw(c1662.5,863.5) 1683,863.5 1683,896.5 ccw(c1662.5,896.5) 1642,896.5 1642,863.5
  lines w32: -1424,715 -1376,715 ; -624,715 -576,715 ; 447.5,863.5 447.5,896.5 ; 1038.5,587.5 1071.5,587.5 ; 1662.5,863.5 1662.5,896.5
  lines w40: -1545.73,950.87 -1545.73,994.87 ; -1254.27,950.87 -1254.27,994.87 ; -745.73,950.87 -745.73,994.87 ; -454.27,950.87 -454.27,994.87
Plane5 (plane layer: these items are gaps in the copper):
  circle w30: c-1615.63,-1146.26 r13
  circle w27: c-1889.37,951.77 r13
  circle w27: c-1889.37,479.33 r13
  circle w27: c-1889.37,6.89 r13
  circle w27: c-1810.63,-465.55 r13
  circle w27: c-1889.37,-465.55 r13
  circle w27: c-1889.37,-701.77 r13
  circle w27: c1889.37,951.77 r13
  circle w27: c1889.37,400.59 r13
  circle w27: c1889.37,-150.59 r13
  circle w27: c1889.37,-701.77 r13
  lines w10: -1630,-645 -1630,-95 -1585,-50 -1585,1025 -1400,1210 -715,1210 -575,1070 1600,1070 1700,970 1700,-910 1275,-1335 10,-1335 5,-1340 -25,-1340 -30,-1335 -940,-1335 -1630,-645 ; -445,-1105 -5,-1105 5,-1095 60,-1095 70,-1105 315,-1105 470,-950 470,-270 345,-145 185.71,-145 ccw(c185.71,-157.48) 173.23,-157.48 cw(c157.48,-157.48) 141.73,-157.48 ccw(c129.25,-157.48) 129.25,-145 122.72,-145 ccw(c122.72,-157.48) 110.24,-157.48 cw(c94.49,-157.48) 78.74,-157.48 ccw(c66.26,-157.48) 66.26,-145 -3.27,-145 ccw(c-3.27,-157.48) -15.75,-157.48 cw(c-31.5,-157.48) -47.24,-157.48 ccw(c-59.73,-157.48) -59.73,-145 -320,-145 -445,-270 -445,-1105
Plane2 (plane layer: these items are gaps in the copper):
  circle w30: c1005,650 r14.5
  circle w30: c1555,650 r14.5
  circle w31: c1630,-900 r15
  circle w27: c1889.37,-701.77 r13
  circle w27: c1889.37,-150.59 r13
  circle w27: c1889.37,400.59 r13
  circle w27: c1889.37,951.77 r13
  circle w27: c-1889.37,951.77 r13
  circle w27: c-1889.37,479.33 r13
  circle w27: c-1889.37,6.89 r13
  circle w27: c-1810.63,-465.55 r13
  circle w27: c-1889.37,-465.55 r13
  circle w27: c-1889.37,-701.77 r13
  lines w10: -1610,405 -735,405 ; -500,-1335 -500,-990 -600,-890 -600,-140 ; -500,-1220 125,-1220 155,-1190 385,-1190 525,-1050 525,-385 300,-160 ; 510,-370 300,-160 ; 525,-425 935,-425 985,-375 1100,-260 1525,-260 ; 825,565 835,565 835,625 -355,625 -405,675 -405,1075 -1610,1075 -1610,130 -1585,105 -1585,-215 -1650,-280 -1650,-1290 -1605,-1335 1480,-1335 1525,-1290 1525,320 1280,565 -575,565 -735,405 ; -735,405 -735,-5 -600,-140 ; -600,-140 245,-140 265,-160 300,-160
  lines w15: 427,863.5 ccw(c447.5,863.5) 468,863.5 468,896.5 ccw(c447.5,896.5) 427,896.5 427,863.5 ; 1038.5,567 cw(c1038.5,587.5) 1038.5,608 1071.5,608 cw(c1071.5,587.5) 1071.5,567 1038.5,567 ; 1642,863.5 ccw(c1662.5,863.5) 1683,863.5 1683,896.5 ccw(c1662.5,896.5) 1642,896.5 1642,863.5
  lines w32: 447.5,863.5 447.5,896.5 ; 1038.5,587.5 1071.5,587.5 ; 1662.5,863.5 1662.5,896.5

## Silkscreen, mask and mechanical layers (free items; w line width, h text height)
Top Overlay:
  region: -1040,-810 -1090,-850 -1040,-890
  region: -750,-810 -800,-850 -750,-890
  lines w6: 1094.65,385.61 1095,365 ; 1113.02,375.01 1095,365 ; 1135.66,435.42 1095,365
  lines w7: -1480,-1315 -1235,-1315 -1235,-1130 -1480,-1130 -1480,-1315 ; -1185,-1380 -1185,-980 -965,-980 -965,-1380 -1185,-1380 ; -1090,-850 -1040,-810 -1040,-890 -1090,-850 ; -800,-850 -750,-890 -750,-810 -800,-850
  text "STATUS" at -584.82,1210.86 h60
  text "POWER / GOOD" at -1635.02,1166.17 h60
  text "FPGA / PROG" at -1195,1165 h60
  text "J3" at -490,1055 h50
  text "J4" at -1615,1050 h50
  text "1" at -1755,960 h32 r270
  text "1" at 1945,960 h32 r270
  text "2" at -1935,940 h32 r90
  text "2" at 1765,940 h32 r90
  text "5" at -1765,800 h32 r270
  text "5" at 1935,800 h32 r270
  text "10" at -1935,620 h32 r90
  text "GND" at -327.5,620 h50
  text "J5" at 80,610 h50
  text "10" at 1765,508.7 h32 r90
  text "#1" at 525,490 h125
  text "J8" at 1000,490 h50
  text "#2" at 1550,490 h125
  text "1.0V" at 1112.07,446.09 h60
  text "15" at -1765,420 h32 r270
  text "15" at 1935,420 h32 r270
  text "J2" at 1756.58,349.39 h50 r90
  text "1.0V" at 1617.07,246.09 h60
  text "20" at -1935,220 h32 r90
  text "J1" at -1750,210 h50 r270
  text "25" at -1765,30 h32 r270
  text "25" at 1935,30 h32 r270
  text "1.8V" at 917.07,-108.89 h60
  text "1.0V" at 1062.07,-108.91 h60
  text "PGOOD" at -1516.4,-169.15 h60
  text "30" at -1935,-175 h32 r90
  text "BOARD ID" at -1230,-245 h45
  text "CTS" at -1005,-365 h30
  text "35" at 1935,-365 h32 r270
  text "TxD" at -1005,-465 h30
  text "40" at -1935,-565 h32 r90
  text "RxD" at -1005,-565 h30
  text "NC" at -1005,-665 h30
  text "43" at 1935,-677.5 h32 r270
  text "(3.3V)" at -695,-680 h30 r90
  text "44" at -1935,-730 h32 r90
  text "RTS" at -1005,-765 h30
  text "IEEE-1394 / ETHERNET  FPGA" at 1580,-775 h67 r90
  text "Rev 3.2 (September 2024)" at 1655,-775 h67 r90
  text "(C) 2010-20224 Johns Hopkins Univ." at 1730,-775 h65 r90
  text "CONSOLE" at -745,-780 h50 r90
  text "GND" at -1615,-790 h50
  text "GND" at -1005,-865 h30
  text "JTAG" at -1360,-870 h50 r90
  text "+" at 1455,-930 h80 r180
  text "0.75V" at -707.39,-954.45 h50
  text "NC" at -1155,-1030 h28
  text "GND" at -1060,-1030 h28
  text "J6" at 1525,-1080 h50
  text "8-16V" at 1660,-1080 h50
  text "NC" at -1155,-1085 h28
  text "GND" at -1060,-1085 h28
  text "1.5V" at -834.14,-1104.45 h50
  text "TDI" at -1165,-1140 h28
  text "GND" at -1060,-1140 h28
  text "3.3V" at -1463.98,-1179 h28
  text "GND" at -1327.32,-1179 h28
  text "TDO" at -1170,-1195 h28
  text "GND" at -1060,-1195 h28
  text "35" at -1438.33,-1239 h28
  text "34" at -1313.33,-1239 h28
  text "TCK" at -1170,-1250 h28
  text "GND" at -1060,-1250 h28
  text "3.3V" at -835.07,-1254.45 h50
  text "37" at -1438.33,-1299 h28
  text "36" at -1313.33,-1299 h28
  text "TMS" at -1170,-1305 h28
  text "GND" at -1060,-1305 h28
  text "VDD" at -1165,-1360 h28
  text "GND" at -1060,-1360 h28
  text "PS I/O" at -1520.01,-1362.46 h50 r90
  text "V-IN" at 1550,-1395 h60
  text "5.0V" at -834.92,-1404.45 h50
  text "GND" at -250,-1405 h50
Bottom Overlay:
  lines w7: -1565,1040 -1565,1315 ; -1235,1040 -1235,1315 ; -765,1040 -765,1315 ; -435,1040 -435,1315
  text "J4" at -1130,1110 h50
  text "J3" at -785,1110 h50
  text "J1" at -1690,25 h40
  text "J2" at 1750,25 h40
  text "3.2V" at 750,-18.91 h60
  text "1.0V" at 1055.87,-18.91 h60
  text "1.0V" at 750,-118.91 h60
  text "1.0V" at 1055.87,-118.91 h60
  text "1.8V" at 750,-218.89 h60
  text "PGOOD" at 1142.79,-219.15 h60
  text "0.75V" at 750,-318.91 h60
  text "1.5V" at 1055.87,-318.91 h60
  text "EN-3V" at 1200,-799.34 h60
  text "3.3V" at 1354.04,-799.34 h60
  text "PWR" at 1520.69,-800 h60
  text "+" at 1513,-950 h35 r180
  text "-" at 1610,-950 h35 r180
  text "5.0V" at 1353.86,-1038.48 h60
  text "PWR" at 1520.69,-1038.34 h60
  text "EN-5V" at 1200,-1043.34 h60
Top Paste:
  circle w4: c955,-1276 r1.5
  circle w4: c925,-1276 r1.5
  circle w4: c969,-1276 r1.5
  circle w4: c911,-1276 r1.5
  circle w4: c947.5,-1314.37 r1.5
  rectangle: -1464,536 -1416,564
  rectangle: -1404,536 -1356,564
  rectangle: -1404,576 -1356,604
  rectangle: -1464,576 -1416,604
  rectangle: -1534,553 -1480,587
  rectangle: -599,-1294 -546,-1246
  region: -611,-1246 -664,-1246 -664,-1294 -611,-1294
  region: -611,-1306 -664,-1306 -664,-1354 -611,-1354
  rectangle: -599,-1354 -546,-1306
  rectangle: -599,-1054 -546,-1006
  region: -611,-1006 -664,-1006 -664,-1054 -611,-1054
  region: -611,-1066 -664,-1066 -664,-1114 -611,-1114
  rectangle: -599,-1114 -546,-1066
  region: -1421,51 -1421,104 -1469,104 -1469,51
  region: -1469,39 -1469,-14 -1421,-14 -1421,39
  region: -1409,39 -1409,-14 -1361,-14 -1361,39
  region: -1361,51 -1361,104 -1409,104 -1409,51
  region: -1661,51 -1661,104 -1709,104 -1709,51
  region: -1709,39 -1709,-14 -1661,-14 -1661,39
  region: -1649,39 -1649,-14 -1601,-14 -1601,39
  region: -1601,51 -1601,104 -1649,104 -1649,51
  rectangle: 1426,-1089 1479,-1041
  region: 1414,-1041 1361,-1041 1361,-1089 1414,-1089
  region: 1414,-1101 1361,-1101 1361,-1149 1414,-1149
  rectangle: 1426,-1149 1479,-1101
  rectangle: 1426,-1329 1479,-1281
  region: 1414,-1281 1361,-1281 1361,-1329 1414,-1329
  region: 1414,-1341 1361,-1341 1361,-1389 1414,-1389
  rectangle: 1426,-1389 1479,-1341
  region: 971,-221 971,-274 1019,-274 1019,-221
  region: 1019,-209 1019,-156 971,-156 971,-209
  region: 959,-209 959,-156 911,-156 911,-209
  region: 911,-221 911,-274 959,-274 959,-221
  region: 731,-221 731,-274 779,-274 779,-221
  region: 779,-209 779,-156 731,-156 731,-209
  region: 719,-209 719,-156 671,-156 671,-209
  region: 671,-221 671,-274 719,-274 719,-221
  region: 559,-401 506,-401 506,-449 559,-449
  rectangle: 571,-449 624,-401
  rectangle: 571,-389 624,-341
  region: 559,-341 506,-341 506,-389 559,-389
  region: 559,-161 506,-161 506,-209 559,-209
  rectangle: 571,-209 624,-161
  rectangle: 571,-149 624,-101
  region: 559,-101 506,-101 506,-149 559,-149
  region: 599,-536 546,-536 546,-584 599,-584
  rectangle: 611,-584 664,-536
  rectangle: 611,-524 664,-476
  region: 599,-476 546,-476 546,-524 599,-524
  region: 599,-776 546,-776 546,-824 599,-824
  rectangle: 611,-824 664,-776
  rectangle: 611,-764 664,-716
  region: 599,-716 546,-716 546,-764 599,-764
  region: 954,-934 954,-881 906,-881 906,-934
  region: 906,-946 906,-999 954,-999 954,-946
  region: 966,-946 966,-999 1014,-999 1014,-946
  region: 1014,-934 1014,-881 966,-881 966,-934
  region: 1194,-934 1194,-881 1146,-881 1146,-934
  region: 1146,-946 1146,-999 1194,-999 1194,-946
  region: 1206,-946 1206,-999 1254,-999 1254,-946
  region: 1254,-934 1254,-881 1206,-881 1206,-934
  region: 834,-934 834,-881 786,-881 786,-934
  region: 786,-946 786,-999 834,-999 834,-946
  region: 846,-946 846,-999 894,-999 894,-946
  region: 894,-934 894,-881 846,-881 846,-934
  region: 594,-934 594,-881 546,-881 546,-934
  region: 546,-946 546,-999 594,-999 594,-946
  region: 606,-946 606,-999 654,-999 654,-946
  region: 654,-934 654,-881 606,-881 606,-934
  rectangle: 466,-1089 519,-1041
  region: 454,-1041 401,-1041 401,-1089 454,-1089
  region: 454,-1101 401,-1101 401,-1149 454,-1149
  rectangle: 466,-1149 519,-1101
  rectangle: 466,-1389 519,-1341
  region: 454,-1341 401,-1341 401,-1389 454,-1389
  region: 454,-1281 401,-1281 401,-1329 454,-1329
  rectangle: 466,-1329 519,-1281
  region: -1011,539 -1047,539 -1047,503 -1011,503
  region: -1069,539 -1105,539 -1105,503 -1069,503
  region: -1069,481 -1105,481 -1105,445 -1069,445
  region: -1011,481 -1047,481 -1047,445 -1011,445
  region: -1011,597 -1047,597 -1047,561 -1011,561
  region: -1069,597 -1105,597 -1105,561 -1069,561
  region: -1069,655 -1105,655 -1105,619 -1069,619
  region: -1011,655 -1047,655 -1047,619 -1011,619
  rectangle: -989,561 -953,597
  rectangle: -931,561 -895,597
  rectangle: -931,619 -895,655
  rectangle: -989,619 -953,655
  rectangle: -989,445 -953,481
  rectangle: -931,445 -895,481
  rectangle: -931,503 -895,539
  rectangle: -989,503 -953,539
Mechanical 1:
  the board outline again, w5
Mechanical 2:
  circle w5: c-1825,-900 r60
  circle w5: c-1825,1150 r60
  circle w5: c1825,1150 r60
  circle w5: c1825,-900 r60
  circle w5: c-1125,-1770 r5
  circle w5: c-1125.5,-1680.5 r3
  region: 675.5,442 675.5,408 690,408 690,442
  region: 763.17,494 763.17,460 777.67,460 777.67,494
  region: 841.91,494 841.91,460 856.41,460 856.41,494
  region: 929.5,442 929.5,408 944,408 944,442
  region: 1479.5,442 1479.5,408 1494,408 1494,442
  region: 1225.5,442 1225.5,408 1240,408 1240,442
  region: 1313.13,494 1313.13,460 1327.63,460 1327.63,494
  region: 1391.87,494 1391.87,460 1406.37,460 1406.37,494
  region: 1356.5,-52.5 1356.5,-86.5 1371,-86.5 1371,-52.5
  region: 1277,205.5 1243,205.5 1243,191 1277,191
  region: 1427,182.5 1393,182.5 1393,168 1427,168
  region: 1527,371.87 1493,371.87 1493,357.37 1527,357.37
  region: 977,371.87 943,371.87 943,357.37 977,357.37
  region: 727,205.5 693,205.5 693,191 727,191
  region: 877,182.5 843,182.5 843,168 877,168
  region: -1549,384.5 -1549,418.5 -1563.5,418.5 -1563.5,384.5
  region: -693,-301.5 -693,-267.5 -707.5,-267.5 -707.5,-301.5
  rectangle: -1146,-1598.5 -1105,-1582.5
  lines w2: 970,-422 970,-386 ; -915,-850 -915,-850
  lines w5: -1150,-1800 -1180,-1800 -1180,-1740 -1150,-1740 ; -1136.5,-1698.5 -1162.5,-1698.5 -1162.5,-1662.5 -1136.5,-1662.5 ; -1130,-1790 -1120,-1790 ; -1130,-1750 -1120,-1750 ; -1128.5,-1693.5 -1122.5,-1693.5 ; -1128.5,-1667.5 -1122.5,-1667.5 ; -1114.5,-1698.5 -1088.5,-1698.5 -1088.5,-1662.5 -1114.5,-1662.5 ; -1100,-1800 -1070,-1800 -1070,-1740 -1100,-1740 ; -1153,-1605.5 -1098,-1605.5 -1098,-1575.5 -1153,-1575.5 -1153,-1605.5
  lines w10: -1425,-2275 -1425,-1850 2300,-1850 ; -1425,-2145 525,-2145 ; 525,-2275 525,-1850 ; -2300,-2275 2300,-2275 2300,1650 -2300,1650 -2300,-2275
  text "Top Assembly Drawing" at -1225,1425 h250
  text "NOTES:" at -2175,-1535 h125
  text "1)" at -2069.24,-1614.94 h80
  text "Components of symbol" at -2000,-1615 h80
  text "in 0201 package are one of CB1-CB75 and have the same values." at -1050,-1615 h80
  text "2)" at -2073.13,-1704.94 h80
  text "Components of symbol" at -2000,-1705 h80
  text "in 0402 package are one of CB76-CB115 and have the same values." at -1050,-1705 h80
  text "3)" at -2072.2,-1794.94 h80
  text "Components of symbol" at -2000,-1795 h80
  text "in 0603 package are one of CB116-CB140 and have the same values." at -1050,-1795 h80
  text "Title:" at -1375,-1950 h100
  text "Johns Hopkins University" at 575,-2000 h150
  text "IEEE-1394/Ethernet FPGA" at -1275,-2075 h150
  text "Laboratory for Computational" at 650,-2125 h100
  text "Sensing and Robotics" at 650,-2225 h100
  text "Date:" at -1375,-2240 h100
  text ".Print_Date" at -1100,-2240 h100
  text "Rev:" at 0,-2240 h100
  text "3.2" at 275,-2240 h100
Mechanical 3:
  circle w5: c-1825,-900 r60
  circle w5: c-1825,1150 r60
  circle w5: c1825,1150 r60
  circle w5: c1825,-900 r60
  circle w5: c1125.5,-1680.5 r3
  circle w5: c1125,-1770 r5
  region: 467,487.5 433,487.5 433,473 467,473
  region: 424.5,389.2 424.5,355.2 439,355.2 439,389.2
  region: 460.5,389.2 460.5,355.2 475,355.2 475,389.2
  region: 1146,-1582.5 1105,-1582.5 1105,-1598.5 1146,-1598.5
  region: 412.5,-308 412.5,-342 427,-342 427,-308
  region: 412.5,-407 412.5,-441 427,-441 427,-407
  region: 349.23,-503.28 349.23,-537.28 363.73,-537.28 363.73,-503.28
  region: 412.5,-495.5 412.5,-529.5 427,-529.5 427,-495.5
  region: 412.5,-584 412.5,-618 427,-618 427,-584
  region: 412.5,-683 412.5,-717 427,-717 427,-683
  region: 355.77,-676.5 355.77,-710.5 370.27,-710.5 370.27,-676.5
  region: 317.74,-755.24 317.74,-789.24 332.24,-789.24 332.24,-755.24
  region: 349.23,-881.23 349.23,-915.23 363.73,-915.23 363.73,-881.23
  region: 349.23,-944.22 349.23,-978.22 363.73,-978.22 363.73,-944.22
  region: -2.75,-124.5 -2.75,-158.5 11.75,-158.5 11.75,-124.5
  region: -101.99,-124.73 -101.99,-158.73 -87.49,-158.73 -87.49,-124.73
  region: -227.5,-283 -227.5,-317 -213,-317 -213,-283
  region: -387.5,-308 -387.5,-342 -373,-342 -373,-308
  region: -332.5,-568 -332.5,-602 -318,-602 -318,-568
  region: -364.23,-534.77 -364.23,-568.77 -349.73,-568.77 -349.73,-534.77
  region: -364.23,-471.78 -364.23,-505.78 -349.73,-505.78 -349.73,-471.78
  region: -432.5,-408 -432.5,-442 -418,-442 -418,-408
  region: -432.5,-533 -432.5,-567 -418,-567 -418,-533
  region: -432.5,-633 -432.5,-667 -418,-667 -418,-633
  region: -367.5,-646.5 -367.5,-680.5 -353,-680.5 -353,-646.5
  region: -367.5,-690.5 -367.5,-724.5 -353,-724.5 -353,-690.5
  region: -332.74,-692.25 -332.74,-726.25 -318.24,-726.25 -318.24,-692.25
  region: -80.77,-660.76 -80.77,-694.76 -66.27,-694.76 -66.27,-660.76
  region: -80.77,-597.76 -80.77,-631.76 -66.27,-631.76 -66.27,-597.76
  region: 24,-455.44 24,-489.44 38.5,-489.44 38.5,-455.44
  region: 65.77,-471.78 65.77,-505.78 80.27,-505.78 80.27,-471.78
  region: 65.77,-534.77 65.77,-568.77 80.27,-568.77 80.27,-534.77
  region: 65.77,-660.76 65.77,-694.76 80.27,-694.76 80.27,-660.76
  region: 97.26,-660.76 97.26,-694.76 111.76,-694.76 111.76,-660.76
  region: 97.26,-755.24 97.26,-789.24 111.76,-789.24 111.76,-755.24
  region: 65.77,-881.23 65.77,-915.23 80.27,-915.23 80.27,-881.23
  region: 65.77,-944.22 65.77,-978.22 80.27,-978.22 80.27,-944.22
  region: -80.77,-881.23 -80.77,-915.23 -66.27,-915.23 -66.27,-881.23
  region: -80.77,-944.22 -80.77,-978.22 -66.27,-978.22 -66.27,-944.22
  region: -364.23,-881.23 -364.23,-915.23 -349.73,-915.23 -349.73,-881.23
  region: -364.23,-944.22 -364.23,-978.22 -349.73,-978.22 -349.73,-944.22
  region: -432.5,-983 -432.5,-1017 -418,-1017 -418,-983
  region: -432.5,-1083 -432.5,-1117 -418,-1117 -418,-1083
  region: -218,-1067.5 -252,-1067.5 -252,-1082 -218,-1082
  region: -323.98,-780.49 -357.98,-780.49 -357.98,-794.99 -323.98,-794.99
  region: -292.49,-497.03 -326.49,-497.03 -326.49,-511.53 -292.49,-511.53
  region: 137.51,-497.03 103.51,-497.03 103.51,-511.53 137.51,-511.53
  region: -72.02,-465.53 -106.02,-465.53 -106.02,-480.03 -72.02,-480.03
  region: -72.02,-560.02 -106.02,-560.02 -106.02,-574.52 -72.02,-574.52
  region: 137.51,-560.02 103.51,-560.02 103.51,-574.52 137.51,-574.52
  region: 106.02,-623.01 72.02,-623.01 72.02,-637.51 106.02,-637.51
  region: -103.51,-654.51 -137.51,-654.51 -137.51,-669.01 -103.51,-669.01
  region: -103.51,-749 -137.51,-749 -137.51,-763.5 -103.51,-763.5
  region: -72.02,-843.49 -106.02,-843.49 -106.02,-857.99 -72.02,-857.99
  region: 357.98,-843.48 323.98,-843.48 323.98,-857.98 357.98,-857.98
  region: 326.49,-654.51 292.49,-654.51 292.49,-669.01 326.49,-669.01
  region: 357.98,-591.52 323.98,-591.52 323.98,-606.02 357.98,-606.02
  region: 357.98,-560.02 323.98,-560.02 323.98,-574.52 357.98,-574.52
  region: 357.98,-465.53 323.98,-465.53 323.98,-480.03 357.98,-480.03
  lines w2: 798,-1318 798,-1282 ; 995,-1306 1007,-1306 1007,-1332 ; 1007,-1380 1007,-1350 ; 1033,-1332 1059,-1332 ; 1077,-997 1077,-983 ; 1081,-1332 1107,-1332 1107,-1344 ; 1082,-1313 1082,-1277 ; 1100,-1800 1070,-1800 1070,-1740 1100,-1740 ; 1114.5,-1698.5 1088.5,-1698.5 1088.5,-1662.5 1114.5,-1662.5 ; 1120,-1790 1130,-1790 ; 1120,-1750 1130,-1750 ; 1122.5,-1693.5 1128.5,-1693.5 ; 1122.5,-1667.5 1128.5,-1667.5 ; 1136.5,-1698.5 1162.5,-1698.5 1162.5,-1662.5 1136.5,-1662.5 ; 1150,-1800 1180,-1800 1180,-1740 1150,-1740 ; 1098,-1605.5 1098,-1575.5 1153,-1575.5 1153,-1605.5 1098,-1605.5
  lines w10: -2300,-1850 1425,-1850 1425,-2275 ; -525,-2275 -525,-1850 ; -525,-2145 1425,-2145 ; -2300,-2275 -2300,1650 2300,1650 2300,-2275 -2300,-2275
  text "Bottom Assembly Drawing" at 1475,1425 h250
  text "NOTES:" at 2175,-1535 h125
  text "in 0201 package are one of CB1-CB75 and have the same values." at 1050,-1615 h80
  text "Components of symbol" at 2000,-1615 h80
  text "1)" at 2069.24,-1614.94 h80
  text "in 0402 package are one of CB76-CB115 and have the same values." at 1050,-1705 h80
  text "Components of symbol" at 2000,-1705 h80
  text "2)" at 2073.13,-1704.94 h80
  text "in 0603 package are one of CB116-CB140 and have the same values." at 1050,-1795 h80
  text "Components of symbol" at 2000,-1795 h80
  text "3)" at 2072.2,-1794.94 h80
  text "Title:" at 1375,-1950 h100
  text "Johns Hopkins University" at -575,-2000 h150
  text "IEEE-1394/Ethernet FPGA" at 1275,-2075 h150
  text "Laboratory for Computational" at -650,-2125 h100
  text "Sensing and Robotics" at -650,-2225 h100
  text "3.2" at -275,-2240 h100
  text "Rev:" at 0,-2240 h100
  text ".Print_Date" at 1100,-2240 h100
  text "Date:" at 1375,-2240 h100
